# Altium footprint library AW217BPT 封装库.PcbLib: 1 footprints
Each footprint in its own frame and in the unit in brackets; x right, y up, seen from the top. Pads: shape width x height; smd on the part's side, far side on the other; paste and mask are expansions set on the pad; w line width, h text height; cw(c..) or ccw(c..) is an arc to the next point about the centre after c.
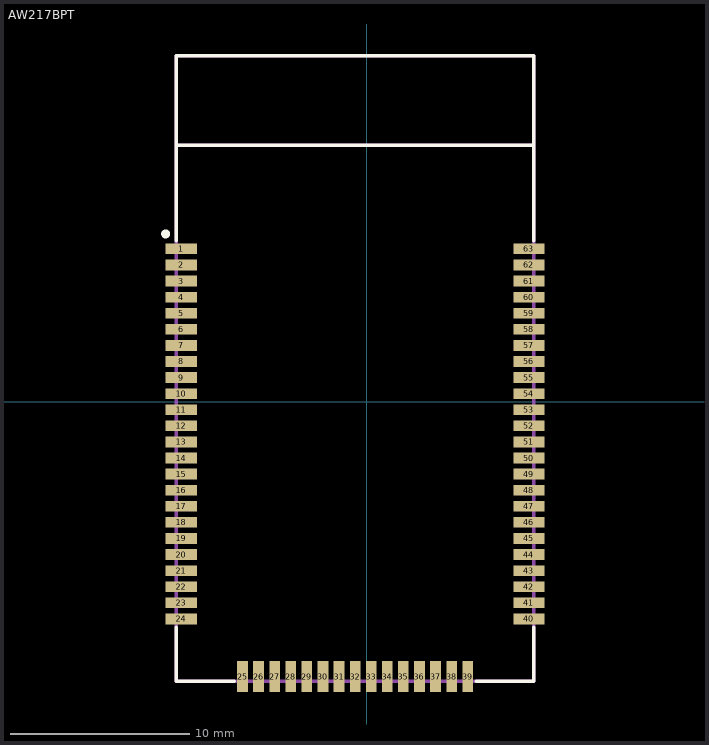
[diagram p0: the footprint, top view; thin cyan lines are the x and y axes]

## AW217BPT [mm]
pads (63):
  rect 1.75x0.6 smd mask+0.051: 1(-10.383,8.563) 2(-10.383,7.663) 3(-10.383,6.763) 4(-10.383,5.863) 5(-10.383,4.963) 6(-10.383,4.063) 7(-10.383,3.163) 8(-10.383,2.263) 9(-10.383,1.363) 10(-10.383,0.463) 11(-10.383,-0.437) 12(-10.383,-1.337) 13(-10.383,-2.237) 14(-10.383,-3.137) 15(-10.383,-4.037) 16(-10.383,-4.937) 17(-10.383,-5.837) 18(-10.383,-6.737) 19(-10.383,-7.637) 20(-10.383,-8.537) 21(-10.383,-9.437) 22(-10.383,-10.337) 23(-10.383,-11.237) 24(-10.383,-12.137) 40(9.067,-12.137) 41(9.067,-11.237) 42(9.067,-10.337) 43(9.067,-9.437) 44(9.067,-8.537) 45(9.067,-7.637) 46(9.067,-6.737) 47(9.067,-5.837) 48(9.067,-4.937) 49(9.067,-4.037) 50(9.067,-3.137) 51(9.067,-2.237) 52(9.067,-1.337) 53(9.067,-0.437) 54(9.067,0.463) 55(9.067,1.363) 56(9.067,2.263) 57(9.067,3.163) 58(9.067,4.063) 59(9.067,4.963) 60(9.067,5.863) 61(9.067,6.763) 62(9.067,7.663) 63(9.067,8.563)
  rect 0.6x1.75 smd mask+0.051: 25(-6.958,-15.362) 26(-6.058,-15.362) 27(-5.158,-15.362) 28(-4.258,-15.362) 29(-3.358,-15.362) 30(-2.458,-15.362) 31(-1.558,-15.362) 32(-0.658,-15.362) 33(0.242,-15.362) 34(1.142,-15.362) 35(2.042,-15.362) 36(2.942,-15.362) 37(3.842,-15.362) 38(4.742,-15.362) 39(5.642,-15.362)
Top Overlay:
  circle w0.25: c-11.258,9.401 r0.125
  lines w0.2: -10.658,-12.606 -10.658,-15.637 -7.431,-15.637 ; -10.658,9.033 -10.658,19.363 9.342,19.363 9.342,9.033 ; -10.658,14.363 9.342,14.363 ; 6.115,-15.637 9.342,-15.637 9.342,-12.606
Mechanical 15:
  lines w0.2: -10.658,14.363 9.342,14.363 ; -10.658,-15.637 -10.658,19.363 9.342,19.363 9.342,-15.637 -10.658,-15.637
  text "天线区域" at -2.958,16.351 h1.52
